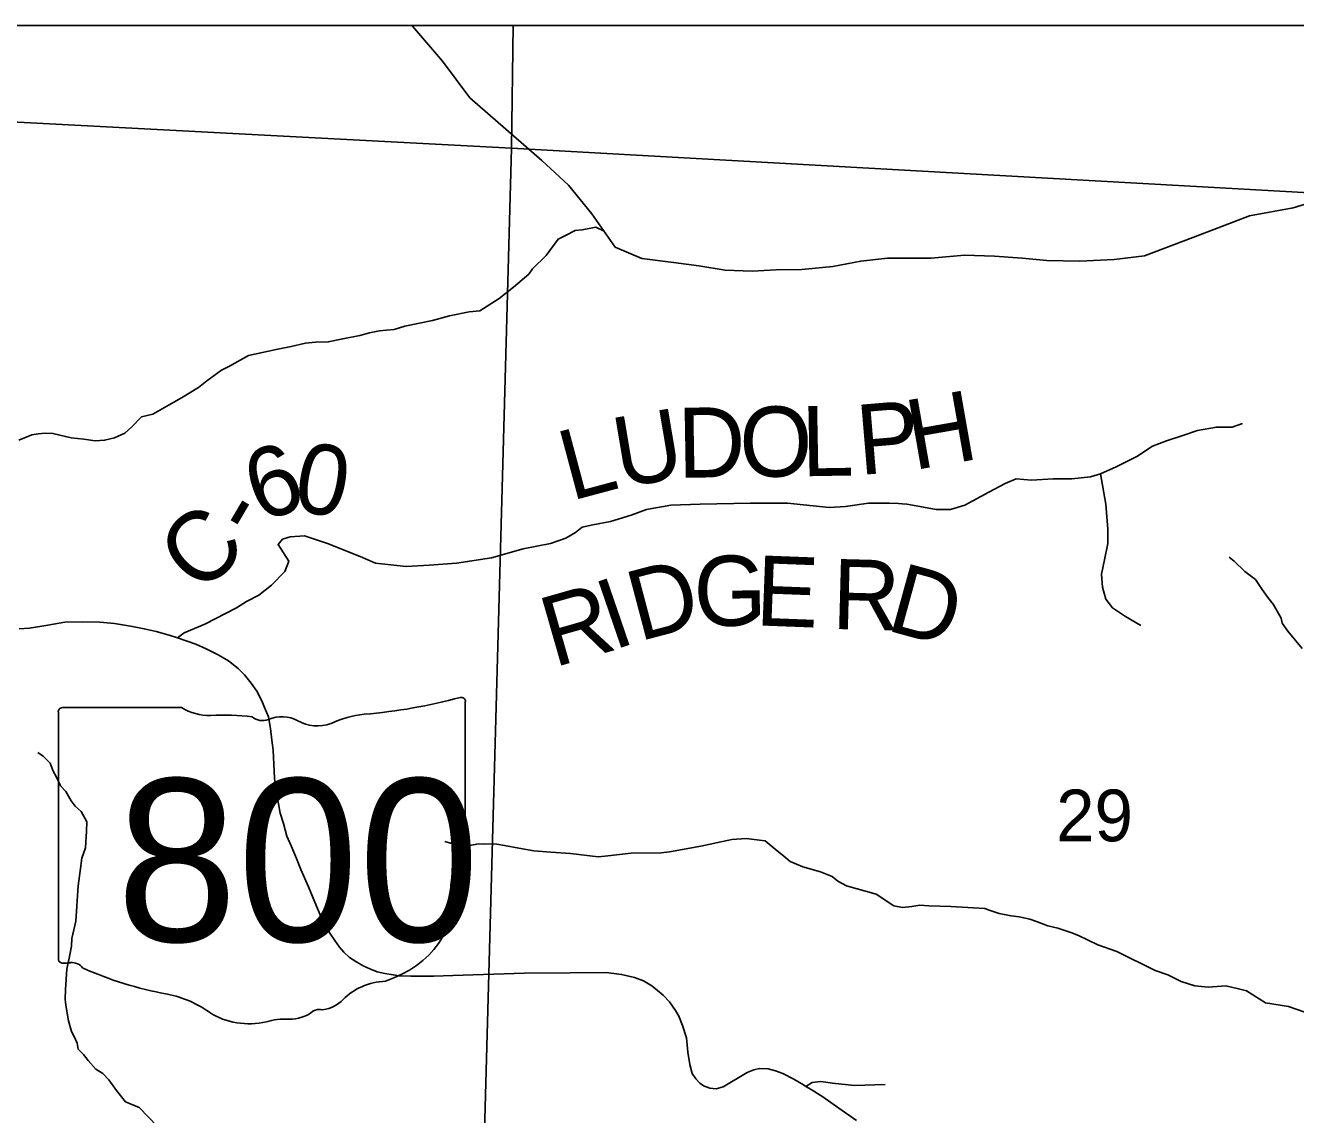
# Model space of a CAD drawing. Extents: x 6.3 to 40.3, y 9 to 31.
# Drawn here: x 13.605 to 14.633, y 29.063 to 29.946 of the extents above; entities that cross this region are included whole.
import ezdxf

# ---------------------------------------------------------------- set-up
doc = ezdxf.new("R2010")
doc.units = 0
for name, color, linetype in [('Default', 7, 'Continuous'), ('GM_X_Corporation', 7, 'Continuous'), ('GM_X_County_Road', 7, 'Continuous'), ('GM_X_County_Road_Text', 7, 'Continuous'), ('GM_X_Minor_River', 7, 'Continuous'), ('GM_X_Section', 7, 'Continuous'), ('GM_X_Section_Text', 7, 'Continuous'), ('GM_X_State_Location', 7, 'Continuous'), ('GM_X_State_Route', 7, 'Continuous'), ('GM_X_State_Shield', 7, 'Continuous'), ('GM_X_Township_Road', 7, 'Continuous'), ('SH_Cut_Line', 7, 'Continuous'), ('SH_Data', 7, 'Continuous')]:
    doc.layers.add(name, color=color, linetype=linetype)

msp = doc.modelspace()

# ---------------------------------------------------------------- linework, layer by layer
at = {"layer": 'Default'}
for points in [[(13.8699, 27.9843), (13.9229, 28.0334), (14.1255, 28.1814), (14.1838, 28.2048), (14.2088, 28.2297), (14.3175, 28.3072), (14.3656, 28.3529), (14.5068, 28.5239), (14.7136, 28.6814), (14.8068, 28.7324), (14.9534, 28.8297), (15.2353, 29.0934), (15.2446, 29.1038), (15.2446, 29.9457), (12.9998, 29.9457), (12.9672, 29.1426), (12.9544, 28.3711), (12.9197, 27.4857)], [(15.2446, 27.6302), (15.2446, 29.9457), (13.1323, 29.9457), (13.13, 29.8856), (13.116, 29.2473), (13.1156, 29.231), (13.1136, 29.1637), (13.0974, 28.6191), (13.0625, 27.76)]]:
    msp.add_lwpolyline(points, dxfattribs=at)
at = {"layer": 'GM_X_Corporation'}
for points in [[(13.9997, 29.9457), (13, 29.9457), (12.9985, 29.8988), (13.9983, 29.8461)], [(14.9834, 29.9457), (13.9997, 29.9457), (13.9983, 29.8461), (14.9774, 29.7913)]]:
    msp.add_lwpolyline(points, close=True, dxfattribs=at)
at = {"layer": 'GM_X_County_Road'}
for points in [[(14.3146, 29.558), (14.3184, 29.5578), (14.329, 29.556), (14.3423, 29.5534), (14.3538, 29.5534), (14.3653, 29.5569), (14.3848, 29.5675), (14.3981, 29.5746), (14.4069, 29.5782), (14.4193, 29.5773), (14.437, 29.5782), (14.4521, 29.5782), (14.4672, 29.5799), (14.4753, 29.5823), (14.4795, 29.5578), (14.4813, 29.5374), (14.4813, 29.5259), (14.4786, 29.5127), (14.476, 29.5011), (14.4769, 29.4905), (14.4795, 29.4808), (14.4849, 29.4737), (14.4955, 29.4666), (14.5079, 29.4595)], [(13.7277, 29.4495), (13.7333, 29.4534), (13.75, 29.4604), (13.7757, 29.4737), (13.7837, 29.479), (13.7936, 29.4841), (13.8039, 29.492), (13.8148, 29.5033), (13.8181, 29.5117), (13.8093, 29.525), (13.8129, 29.5294), (13.8191, 29.5312), (13.8306, 29.5321), (13.8492, 29.5259), (13.8757, 29.5153), (13.8881, 29.51), (13.9129, 29.5073), (13.9315, 29.5082), (13.9537, 29.51), (13.982, 29.5144), (14.0077, 29.5215), (14.0298, 29.5259), (14.0422, 29.5303), (14.0502, 29.5348), (14.0555, 29.5392), (14.0643, 29.541), (14.0785, 29.5436), (14.0953, 29.5489), (14.1077, 29.5534), (14.1272, 29.5569), (14.1511, 29.5578), (14.1918, 29.5587), (14.2219, 29.5587), (14.2556, 29.5551), (14.2688, 29.556), (14.2874, 29.5587), (14.3042, 29.5587), (14.3118, 29.5582), (14.3146, 29.558)]]:
    msp.add_lwpolyline(points, dxfattribs=at)
at = {"layer": 'GM_X_Minor_River'}
for points in [[(14.6562, 29.8054), (14.6312, 29.7979), (14.596, 29.7914), (14.5578, 29.7767), (14.5109, 29.759), (14.4863, 29.756), (14.4586, 29.7548), (14.4317, 29.7552), (14.4117, 29.7571), (14.3893, 29.7586), (14.3651, 29.7594), (14.3382, 29.7571), (14.3027, 29.7571), (14.2811, 29.7548), (14.2584, 29.7503), (14.2334, 29.748), (14.2126, 29.7476), (14.1932, 29.7465), (14.1713, 29.7473), (14.1501, 29.751), (14.1296, 29.7537), (14.1039, 29.7567), (14.0823, 29.7661), (14.0634, 29.7929), (14.0445, 29.8163), (14.0229, 29.8363), (13.9646, 29.8869), (13.9423, 29.9167), (13.918, 29.945), (13.9174, 29.9457)], [(14.0733, 29.7789), (14.0665, 29.7823), (14.0555, 29.7801), (14.0498, 29.7796), (14.042, 29.7756), (14.036, 29.7725), (14.0264, 29.7593), (14.0152, 29.7484), (14.0123, 29.7442), (14, 29.7337), (13.9884, 29.7243), (13.9727, 29.7144), (13.964, 29.7135), (13.9481, 29.7105), (13.9342, 29.7067), (13.9119, 29.702), (13.9032, 29.6992), (13.8972, 29.6987), (13.8915, 29.6982), (13.8832, 29.6965), (13.8756, 29.6944), (13.8616, 29.6918), (13.8499, 29.6893), (13.8397, 29.689), (13.8314, 29.6881), (13.82, 29.6855), (13.8076, 29.683), (13.7853, 29.6783), (13.7699, 29.6696), (13.7635, 29.6664), (13.7516, 29.6578), (13.7449, 29.6523), (13.731, 29.644), (13.7231, 29.6393), (13.7078, 29.6306), (13.6987, 29.6285), (13.6909, 29.6203), (13.6853, 29.6153), (13.6767, 29.6116), (13.6688, 29.6096), (13.6612, 29.609), (13.652, 29.6103), (13.6418, 29.6116), (13.6269, 29.6151), (13.6208, 29.6153), (13.6151, 29.6148), (13.6098, 29.6139), (13.5993, 29.6095)], [(14.6387, 29.4407), (14.627, 29.4548), (14.6223, 29.4612), (14.6215, 29.4654), (14.6151, 29.4766), (14.6108, 29.4822), (14.6061, 29.4886), (14.6007, 29.4968), (14.5922, 29.5031), (14.5836, 29.5116), (14.5794, 29.5149)], [(13.6369, 29.1566), (13.6372, 29.1646), (13.6383, 29.181), (13.6404, 29.1913), (13.6421, 29.1997), (13.6423, 29.2058), (13.6454, 29.2199), (13.6475, 29.2485), (13.6494, 29.2626), (13.6504, 29.271), (13.6532, 29.2794), (13.6541, 29.2927), (13.6543, 29.3003), (13.6499, 29.3086), (13.6449, 29.313), (13.6418, 29.3175), (13.6374, 29.325), (13.6332, 29.3295), (13.6296, 29.337), (13.6272, 29.3415), (13.6248, 29.3479), (13.619, 29.3535), (13.6147, 29.3564)], [(14.6406, 29.1462), (14.6276, 29.1508), (14.6089, 29.1538), (14.5935, 29.1634), (14.5871, 29.1651), (14.5768, 29.1675), (14.5624, 29.1665), (14.5517, 29.1674), (14.5406, 29.1709), (14.5299, 29.1764), (14.5196, 29.1799), (14.4885, 29.1952), (14.4732, 29.2006), (14.4575, 29.2082), (14.4513, 29.2107), (14.4406, 29.2143), (14.4326, 29.216), (14.4234, 29.2196), (14.4181, 29.2214), (14.4093, 29.2234), (14.4028, 29.2241), (14.3933, 29.2261), (14.386, 29.2286), (14.3815, 29.23), (14.3541, 29.2317), (14.3362, 29.2324), (14.329, 29.2327), (14.3226, 29.2318), (14.315, 29.2308), (14.3078, 29.2322), (14.2935, 29.2417), (14.2695, 29.2484), (14.2626, 29.2524), (14.2579, 29.2561), (14.2484, 29.2597), (14.2342, 29.264), (14.2239, 29.2683), (14.2189, 29.2724), (14.2119, 29.2783), (14.2038, 29.2849), (14.1992, 29.2856), (14.1882, 29.2869), (14.1768, 29.2859), (14.1515, 29.2807), (14.1262, 29.276), (14.1194, 29.2751), (14.0951, 29.2749), (14.0739, 29.2725), (14.0686, 29.272), (14.0461, 29.2746), (14.0302, 29.2757), (14.0165, 29.2769), (14.0043, 29.2789), (13.9925, 29.2813), (13.9864, 29.2823), (13.9754, 29.2825), (13.9701, 29.2823), (13.9659, 29.2815), (13.9598, 29.281), (13.9526, 29.2819), (13.9442, 29.2844)], [(13.7117, 29.0534), (13.6969, 29.069), (13.6858, 29.0734), (13.6784, 29.0827), (13.6722, 29.0913), (13.6675, 29.0965), (13.6617, 29.0998), (13.6555, 29.1069), (13.6516, 29.1117), (13.6473, 29.1162), (13.6465, 29.1211), (13.6441, 29.1264), (13.6421, 29.1305), (13.6396, 29.1392), (13.6374, 29.1517), (13.6369, 29.1566)]]:
    msp.add_lwpolyline(points, dxfattribs=at)
at = {"layer": 'GM_X_Section'}
for points in [[(12.9985, 29.8988), (13.9983, 29.8461), (13.9707, 28.8429), (12.9705, 28.903), (12.9779, 29.1462)], [(13.9983, 29.8461), (14.9774, 29.7913), (14.9465, 28.9149), (14.9325, 28.8696), (14.9246, 28.8604), (14.9108, 28.8511), (14.8984, 28.8437), (14.892, 28.8386), (14.8845, 28.8344), (14.8687, 28.8258), (14.8481, 28.8126), (14.8335, 28.8028), (14.8222, 28.7974), (14.7965, 28.7913), (13.9707, 28.8429)]]:
    msp.add_lwpolyline(points, close=True, dxfattribs=at)
at = {"layer": 'GM_X_State_Route'}
msp.add_lwpolyline([(14.2778, 29.0584), (14.2635, 29.0683), (14.2504, 29.0775), (14.2409, 29.0835), (14.2366, 29.086), (14.2347, 29.0871), (14.2269, 29.0918), (14.218, 29.0965), (14.2122, 29.0987), (14.2061, 29.1001), (14.199, 29.1005), (14.1945, 29.0993), (14.1892, 29.0973), (14.1697, 29.0856), (14.1641, 29.084), (14.1589, 29.0846), (14.1538, 29.0863), (14.1508, 29.0887), (14.1475, 29.092), (14.1445, 29.0964), (14.1426, 29.1038), (14.1412, 29.1136), (14.1399, 29.1252), (14.1368, 29.1354), (14.1337, 29.1429), (14.131, 29.1476), (14.1262, 29.1545), (14.1211, 29.1599), (14.112, 29.1674), (14.1052, 29.1714), (14.098, 29.1742), (14.0875, 29.1767), (14.0749, 29.1783), (14.0458, 29.178), (14.0087, 29.1777), (13.9507, 29.1758), (13.9354, 29.1752), (13.9259, 29.1752), (13.9169, 29.1753), (13.9072, 29.1756), (13.9025, 29.1764), (13.8958, 29.1775), (13.8895, 29.1789), (13.8835, 29.1811), (13.8787, 29.1834), (13.8731, 29.1866), (13.8672, 29.1903), (13.8626, 29.1948), (13.8589, 29.1987), (13.8552, 29.2042), (13.8511, 29.2102), (13.8483, 29.2149), (13.8443, 29.2232), (13.8404, 29.2321), (13.8338, 29.2477), (13.8277, 29.2618), (13.8243, 29.2707), (13.8198, 29.281), (13.8165, 29.2887), (13.8136, 29.2989), (13.8109, 29.3073), (13.8095, 29.3148), (13.8078, 29.3242), (13.8065, 29.3356), (13.8059, 29.3471), (13.8054, 29.3585), (13.8042, 29.3666), (13.8031, 29.3761), (13.8014, 29.3853), (13.7984, 29.3929), (13.7961, 29.3985), (13.792, 29.4063), (13.7875, 29.4127), (13.7822, 29.4194), (13.7769, 29.4247), (13.769, 29.4308), (13.7607, 29.4356), (13.7511, 29.4404), (13.7428, 29.4442), (13.7277, 29.4495), (13.7211, 29.4517), (13.7105, 29.4546), (13.7009, 29.4568), (13.6915, 29.4585), (13.6769, 29.461), (13.6649, 29.4621), (13.6508, 29.4624), (13.6365, 29.4621), (13.6227, 29.4597), (13.608, 29.4574), (13.5997, 29.4568)], dxfattribs=at)
at = {"layer": 'GM_X_State_Shield'}
for p, q in [((13.9609, 29.2931), (13.9609, 29.3978)), ((13.6314, 29.3894), (13.6314, 29.1893)), ((13.7311, 29.3929), (13.6346, 29.3929)), ((13.9609, 29.2932), (13.9609, 29.2931))]:
    msp.add_line(p, q, dxfattribs=at)
for centre, major_axis, start_param, end_param in [((13.8435, 29.6657), (0.3495, 0), 4.814394, 5.042369), ((13.9573, 29.3983), (0.00367, 0), 6.141152, 7.989035), ((13.6351, 29.3899), (0.00382, 0), 1.712693, 3.28349), ((13.7541, 29.4161), (0.037, 0), 4.042523, 4.731795), ((13.7664, 29.2805), (0.133, 0), 1.404758, 1.657858), ((13.8881, 29.3317), (0.0703, 0), 1.699011, 2.107814), ((13.7966, 29.3909), (0.0107, 0), 3.836095, 5.185415), ((13.8123, 29.3678), (0.0222, 0), 0.950623, 2.079405), ((13.8409, 29.3995), (0.0267, 0), 4.081561, 5.145723), ((13.9601, 29.2855), (0.00568, 0), 1.883978, 3.671073), ((13.957, 29.2927), (0.00393, 0), 5.05454, 6.418171), ((13.924, 29.2722), (0.0341, 0), 5.934695, 6.695948), ((13.9741, 29.2493), (0.0248, 0), 2.387724, 3.262537), ((13.8631, 29.236), (0.0874, 0), 5.101752, 6.440018), ((13.6352, 29.1889), (0.00385, 0), 3.00124, 4.508301), ((13.6358, 29.2093), (0.0294, 0), 4.665946, 4.897461), ((13.6418, 29.1778), (0.0106, 0), 0.519207, 1.627899), ((13.7756, 29.3576), (0.2524, 0), 4.195997, 4.488961), ((13.9, 29.1331), (0.0479, 0), 1.647645, 2.488434), ((13.7003, 29.0994), (0.079, 0), 0.823519, 1.323587), ((13.8393, 29.1699), (0.0282, 0), 4.937069, 5.64225), ((13.7858, 29.1768), (0.0501, 0), 4.026481, 4.996735), ((13.8147, 29.1076), (0.0412, 0), 1.495662, 1.94098), ((13.8184, 29.1618), (0.0267, 0), 4.691044, 5.507374), ((13.8425, 29.1424), (0.00752, 0), 1.147584, 2.315152)]:
    msp.add_ellipse(centre, major_axis=major_axis, ratio=0.8, start_param=start_param, end_param=end_param, dxfattribs=at)
at = {"layer": 'GM_X_Township_Road'}
for points in [[(14.4753, 29.5823), (14.488, 29.588), (14.5048, 29.5964), (14.5174, 29.6048), (14.5286, 29.609), (14.5412, 29.6132), (14.5538, 29.6174), (14.5692, 29.6202), (14.5818, 29.6202), (14.5902, 29.623)], [(14.2366, 29.086), (14.2418, 29.0891), (14.2489, 29.0899), (14.2582, 29.0887), (14.2761, 29.0868), (14.3008, 29.0874)]]:
    msp.add_lwpolyline(points, dxfattribs=at)
at = {"layer": 'SH_Cut_Line'}
msp.add_lwpolyline([(13.8699, 27.9843), (13.9229, 28.0334), (14.1255, 28.1814), (14.1838, 28.2048), (14.2088, 28.2297), (14.3175, 28.3072), (14.3656, 28.3529), (14.5068, 28.5239), (14.7136, 28.6814), (14.8068, 28.7324), (14.9534, 28.8297), (15.2353, 29.0934), (15.2446, 29.1038), (15.2446, 29.9457), (8.4446, 29.9457)], dxfattribs=at)
at = {"layer": 'SH_Data'}
msp.add_line((8.4446, 29.9457), (15.2446, 29.9457), dxfattribs=at)

# ---------------------------------------------------------------- texts
at = {"layer": 'GM_X_County_Road_Text'}
for s, rotation, p in [('H', 9.9612, (14.3239, 29.5852)), ('U', 9.5444, (14.0861, 29.5709)), ('D', 0.9472, (14.1332, 29.579)), ('O', 0.5537, (14.1831, 29.5798)), ('L', 0.9949, (14.2335, 29.5803)), ('P', 4.8156, (14.2802, 29.5813)), ('L', 14.9499, (14.0464, 29.5603)), ('6', 19.5566, (13.7947, 29.5425)), ('0', 349.6555, (13.8197, 29.5535)), ('C', 43.191, (13.7461, 29.4835)), ('-', 59.6267, (13.7909, 29.5291)), ('D', 14.7687, (14.1015, 29.4464)), ('G', 0.9982, (14.1463, 29.4587)), ('E', 357.8074, (14.1954, 29.4596)), ('R', 358.4943, (14.2574, 29.4567)), ('D', 344.6578, (14.3005, 29.456)), ('R', 16.0065, (14.0326, 29.4253)), ('I', 18.9426, (14.0805, 29.4392))]:
    msp.add_text(s, height=0.0568, rotation=rotation, dxfattribs=at).set_placement(p)
at = {"layer": 'GM_X_Section_Text'}
msp.add_text('29', height=0.04186, rotation=0, dxfattribs=at).set_placement((14.4393, 29.2846))
at = {"layer": 'GM_X_State_Location'}
for s in ['s', 'r']:
    msp.add_text(s, height=0.000189, dxfattribs=at).set_placement((13.7924, 29.2761))
msp.add_text('800', height=0.000189, rotation=0, dxfattribs=at).set_placement((13.7256, 29.2623))
at = {"layer": 'GM_X_State_Shield'}
msp.add_text('800', height=0.13184, dxfattribs=at).set_placement((13.6783, 29.2034))

doc.saveas('drawing.dxf')
